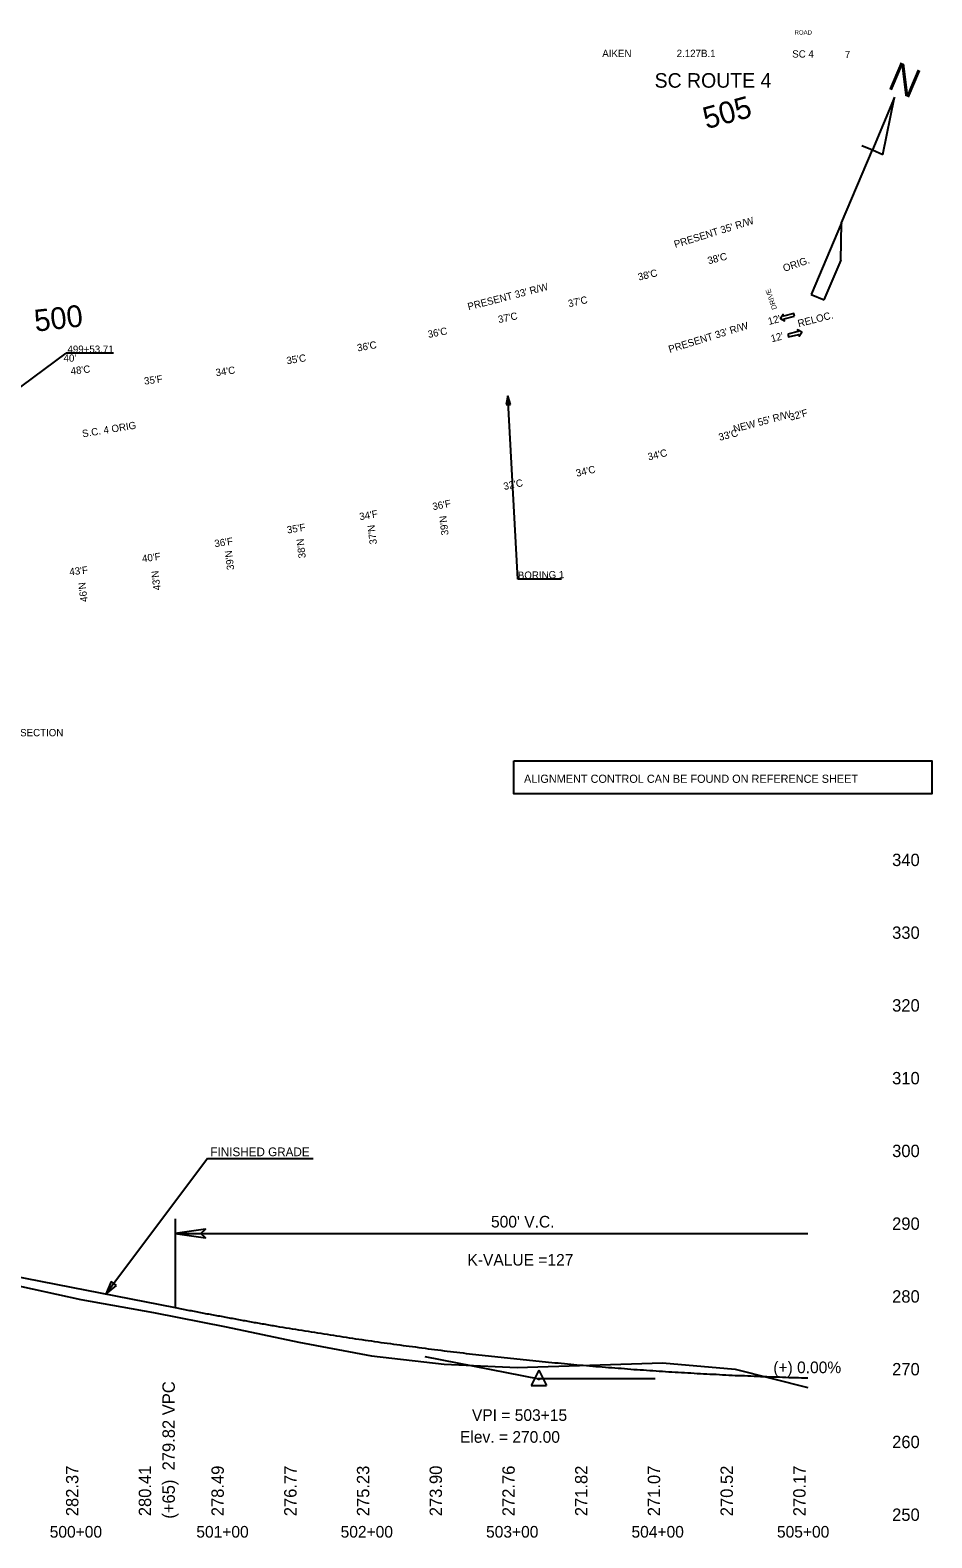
# Model space of a CAD drawing. Extents: x 49105 to 50775, y 45514 to 53458.
# Drawn here: x 50153 to 50773, y 46664 to 47700 of the extents above; entities that cross this region are included whole.
import ezdxf

# ---------------------------------------------------------------- set-up
doc = ezdxf.new("R2010")
doc.units = 0
for name, color, linetype in [('Level 1', 7, 'Continuous'), ('Level 14', 7, 'Continuous'), ('Level 19', 7, 'Continuous'), ('Level 2', 7, 'Continuous'), ('Level 20', 7, 'Continuous'), ('Level 21', 7, 'Continuous'), ('Level 24', 7, 'Continuous'), ('Level 25', 7, 'Continuous'), ('Level 29', 7, 'Continuous'), ('Level 33', 7, 'Continuous'), ('Level 40', 7, 'Continuous'), ('Level 41', 7, 'Continuous'), ('Level 42', 7, 'Continuous'), ('Level 43', 7, 'Continuous'), ('Level 45', 7, 'Continuous'), ('Level 48', 7, 'Continuous'), ('Level 8', 7, 'Continuous')]:
    doc.layers.add(name, color=color, linetype=linetype)

msp = doc.modelspace()

# ---------------------------------------------------------------- linework, layer by layer
at = {"layer": 'Level 1'}
for p, q in [((50488.5, 47322.6), (50481.6, 47448.5)), ((50518.4, 47322.6), (50488.5, 47322.6)), ((50275, 46924.4), (50205.2, 46831.3)), ((50275, 46924.4), (50347.8, 46924.4)), ((50502.9, 46778.9), (50497.7, 46768.4)), ((50502.9, 46778.9), (50508.2, 46768.4)), ((50497.7, 46768.4), (50508.2, 46768.4))]:
    msp.add_line(p, q, dxfattribs=at)
msp.add_lwpolyline([(50252.9, 46872.9), (50273.7, 46869.9), (50270.5, 46872.9), (50273.7, 46875.8)], close=True, dxfattribs=at)
msp.add_circle((50502.9, 46772.9), 0.375, dxfattribs=at)
at = {"layer": 'Level 14'}
for points in [[(50678.7, 47503.2), (50678.2, 47505.1), (50671.1, 47503.3), (50670.8, 47504.5), (50669.1, 47501.8), (50671.9, 47500.2), (50671.6, 47501.4)], [(50674, 47490.9), (50674.5, 47489.1), (50681.6, 47490.8), (50681.9, 47489.6), (50683.6, 47492.3), (50680.8, 47494), (50681.2, 47492.7)]]:
    msp.add_lwpolyline(points, close=True, dxfattribs=at)
at = {"layer": 'Level 2'}
for p, q in [((50747.5, 47653.7), (50732.2, 47617.6)), ((50739.4, 47614.5), (50747.5, 47653.7)), ((50747.5, 47653.7), (50747.5, 47653.7)), ((50725, 47620.6), (50732.2, 47617.6)), ((50710.9, 47567.5), (50732.2, 47617.6)), ((50732.2, 47617.6), (50739.4, 47614.5)), ((50739.4, 47614.5), (50739.6, 47614.9)), ((50710.9, 47567.5), (50690.1, 47518.3)), ((50710.6, 47541.6), (50710.9, 47567.5)), ((50699.1, 47514.5), (50710.7, 47541.8)), ((50710.7, 47541.8), (50710.6, 47541.6)), ((50690.1, 47518.3), (50699.1, 47514.5))]:
    msp.add_line(p, q, dxfattribs=at)
at = {"layer": 'Level 24'}
for p, q in [((50481.6, 47448.5), (50480.4, 47442.5)), ((50483.4, 47442.6), (50481.6, 47448.5)), ((50480.4, 47442.5), (50483.4, 47442.6)), ((50208.8, 46839.9), (50205.2, 46831.3)), ((50205.2, 46831.3), (50212.4, 46837.2)), ((50212.4, 46837.2), (50208.8, 46839.9))]:
    msp.add_line(p, q, dxfattribs=at)
at = {"layer": 'Level 25'}
msp.add_lwpolyline([(50485.8, 47197.7), (50773.1, 47197.7), (50773.1, 47175), (50485.8, 47175)], close=True, dxfattribs=at)
at = {"layer": 'Level 33'}
for p in [(50132.5, 47444.1), (50210.4, 47477.9)]:
    msp.add_line(p, (50177.8, 47477.9), dxfattribs=at)
at = {"layer": 'Level 40'}
msp.add_lwpolyline([(50137.9, 46838.5), (50187.9, 46827.6), (50237.9, 46818.6), (50287.9, 46808.7), (50337.9, 46798.2), (50387.9, 46788.8), (50437.9, 46783.2), (50487.9, 46780.7), (50537.9, 46782.4), (50587.9, 46783.9), (50637.9, 46779.7), (50687.9, 46767.1)], dxfattribs=at)
at = {"layer": 'Level 41'}
for p, q in [((50252.9, 46882.9), (50252.9, 46822)), ((50252.9, 46872.9), (50687.9, 46872.9)), ((50424.4, 46788.3), (50502.9, 46772.9)), ((50582.9, 46772.9), (50502.9, 46772.9))]:
    msp.add_line(p, q, dxfattribs=at)
at = {"layer": 'Level 45'}
msp.add_line((50037.9, 46864.2), (50252.9, 46822), dxfattribs=at)
msp.add_spline([(50252.9, 46822), (50261.6, 46820.3), (50270.3, 46818.6), (50279, 46817), (50287.7, 46815.4), (50296.4, 46813.8), (50305.1, 46812.2), (50313.8, 46810.7), (50322.5, 46809.2), (50331.2, 46807.8), (50339.9, 46806.4), (50348.6, 46805), (50357.3, 46803.6), (50366, 46802.3), (50374.7, 46800.9), (50383.4, 46799.7), (50392.1, 46798.4), (50400.8, 46797.2), (50409.5, 46796), (50418.2, 46794.9), (50426.9, 46793.7), (50435.6, 46792.6), (50444.3, 46791.6), (50453, 46790.5), (50461.7, 46789.5), (50470.4, 46788.5), (50479.1, 46787.6), (50487.8, 46786.7), (50496.5, 46785.8), (50505.2, 46784.9), (50513.9, 46784.1), (50522.6, 46783.3), (50531.3, 46782.5), (50540, 46781.8), (50548.7, 46781), (50557.4, 46780.4), (50566.1, 46779.7), (50574.8, 46779.1), (50583.5, 46778.5), (50592.2, 46777.9), (50600.9, 46777.4), (50609.6, 46776.9), (50618.3, 46776.4), (50627, 46776), (50635.7, 46775.5), (50644.4, 46775.2), (50653.1, 46774.8), (50661.8, 46774.5), (50670.5, 46774.2), (50679.2, 46773.9), (50687.9, 46773.7)], degree=3, dxfattribs=at)

# ---------------------------------------------------------------- texts
at = {"layer": 'Level 1'}
for s, rotation, p in [("PRESENT 35' R/W ", 17.1046, (50596.7, 47550.1)), ('ORIG.', 18.9509, (50671.7, 47533.7)), ("PRESENT 33' R/W ", 14.3539, (50454.6, 47507.3)), ('RELOC.', 14.3587, (50681.6, 47495.7)), ("PRESENT 33' R/W ", 17.1046, (50592.9, 47478)), ('BORING 1', 1, (50488.5, 47322.7))]:
    msp.add_text(s, height=5, rotation=rotation, dxfattribs=at).set_placement(p)
msp.add_text('FINISHED GRADE', height=6, dxfattribs=at).set_placement((50277.1, 46926))
at = {"layer": 'Level 19'}
for s, rotation, p in [('505', 15.2461, (50618.1, 47631.7)), ('500', 6.4962, (50156.8, 47492.6))]:
    msp.add_text(s, height=15, rotation=rotation, dxfattribs=at).set_placement(p)
at = {"layer": 'Level 2'}
msp.add_text('N', height=20, rotation=337, dxfattribs=at).set_placement((50741.7, 47660.2))
at = {"layer": 'Level 20'}
for p in [(50661.1, 47497.2), (50663.1, 47485.3)]:
    msp.add_text("12'", height=5, rotation=14.736, dxfattribs=at).set_placement(p)
at = {"layer": 'Level 21'}
msp.add_text('S.C. 4 ORIG', height=5, rotation=9.2994, dxfattribs=at).set_placement((50189.3, 47420))
at = {"layer": 'Level 24'}
for s, height, p in [('ROAD', 3, (50678.7, 47696.8)), ('AIKEN', 5, (50546.5, 47681.4)), (' 2.127B.1', 5, (50595.8, 47681.4)), ('SC 4', 5, (50677.1, 47681)), ('7', 5, (50713.3, 47680.6)), ('SC ROUTE 4', 10, (50582.5, 47660.3))]:
    msp.add_text(s, height=height, dxfattribs=at).set_placement(p)
at = {"layer": 'Level 25'}
msp.add_text('ALIGNMENT CONTROL CAN BE FOUND ON REFERENCE SHEET', height=5.6, dxfattribs=at).set_placement((50492.7, 47182.6))
at = {"layer": 'Level 29'}
msp.add_text(' PLACE 2 - 18" BEVELED END SECTION', height=5, dxfattribs=at).set_placement((50050.6, 47214.6))
at = {"layer": 'Level 33'}
for s, p in [("40'", (50176.1, 47472)), ('499+53.71', (50178.8, 47478.1))]:
    msp.add_text(s, height=5, dxfattribs=at).set_placement(p)
msp.add_text("NEW 55' R/W", height=5, rotation=14.8068, dxfattribs=at).set_placement((50637.3, 47423.3))
at = {"layer": 'Level 41'}
for s, p in [("500' V.C.", (50470, 46877)), ('K-VALUE =127', (50453.8, 46850.8)), ('(+) 0.00%', (50664.1, 46776.9)), ('VPI = 503+15', (50456.9, 46744.1)), ('Elev. = 270.00', (50448.7, 46729.1))]:
    msp.add_text(s, height=8, dxfattribs=at).set_placement(p)
msp.add_text('(+65)  279.82 VPC', height=8.5, rotation=90, dxfattribs=at).set_placement((50252.6, 46676.9))
at = {"layer": 'Level 42'}
for s, height, p in [('340', 8.5, (50745.8, 47125.4)), ('330', 8.5, (50745.8, 47075.4)), ('320', 8.5, (50745.8, 47025.4)), ('310', 8.5, (50745.8, 46975.4)), ('300', 8.5, (50745.8, 46925.4)), ('290', 8.5, (50745.8, 46875.4)), ('280', 8.5, (50745.8, 46825.4)), ('270', 8.5, (50745.8, 46775.4)), ('260', 8.5, (50745.8, 46725.4)), ('250', 8.5, (50745.8, 46675.4)), ('500+00', 8, (50166.6, 46663.9)), ('501+00', 8, (50267.4, 46663.9)), ('502+00', 8, (50366.6, 46663.9)), ('503+00', 8, (50466.6, 46663.9)), ('504+00', 8, (50566.6, 46663.9)), ('505+00', 8, (50666.6, 46663.9))]:
    msp.add_text(s, height=height, dxfattribs=at).set_placement(p)
at = {"layer": 'Level 43'}
for s, p in [('282.37', (50186.3, 46678.6)), ('280.41', (50236.3, 46678.6)), ('278.49', (50286.3, 46678.6)), ('276.77', (50336.3, 46678.6)), ('275.23', (50386.3, 46678.6)), ('273.90', (50436.3, 46678.6)), ('272.76', (50486.3, 46678.6)), ('271.82', (50536.3, 46678.6)), ('271.07', (50586.3, 46678.6)), ('270.52', (50636.3, 46678.6)), ('270.17', (50686.3, 46678.6))]:
    msp.add_text(s, height=8.5, rotation=90, dxfattribs=at).set_placement(p)
at = {"layer": 'Level 48'}
for s, rotation, p in [("38'C", 14.3711, (50619.6, 47538.9)), ("38'C", 13.4961, (50571.7, 47527.7)), ("37'C", 12.6212, (50523.6, 47509.4)), ("37'C", 11.7461, (50475.4, 47498.5)), ("36'C", 10.8711, (50427, 47488.3)), ("36'C", 9.9961, (50378.4, 47479)), ("35'C", 9.1211, (50329.8, 47470.2)), ("48'C", 6.4961, (50181.3, 47463.1)), ("34'C", 8.2462, (50281, 47462)), ("35'F", 7.3711, (50231.8, 47456.2)), ("32'F", 15.2461, (50675.9, 47431.4)), ("33'C", 14.3711, (50627.2, 47417.6)), ("34'C", 13.4961, (50578.4, 47404.1)), ("34'C", 12.6211, (50529, 47392.9)), ("32'C", 11.7461, (50479.1, 47383.8)), ("36'F", 10.8711, (50430.2, 47369.9)), ("35'F", 9.1212, (50330.1, 47353.9)), ("34'F", 9.9962, (50379.9, 47363)), ("39'N", 96.917, (50440.9, 47353)), ("36'F", 8.2462, (50280.2, 47344.5)), ("37'N", 96.917, (50391.6, 47346.7)), ("40'F", 7.3711, (50230.4, 47334.2)), ("39'N", 96.917, (50293.5, 47329.1)), ("38'N", 96.917, (50342.7, 47337.2)), ("43'F", 6.4962, (50180.4, 47325.1)), ("46'N", 96.917, (50192.7, 47307.2)), ("43'N", 96.917, (50242.9, 47315.2))]:
    msp.add_text(s, height=5, rotation=rotation, dxfattribs=at).set_placement(p)
at = {"layer": 'Level 8'}
msp.add_text('DRIVE', height=3.5, rotation=108.8976, dxfattribs=at).set_placement((50666.7, 47508.5))

doc.saveas('drawing.dxf')
